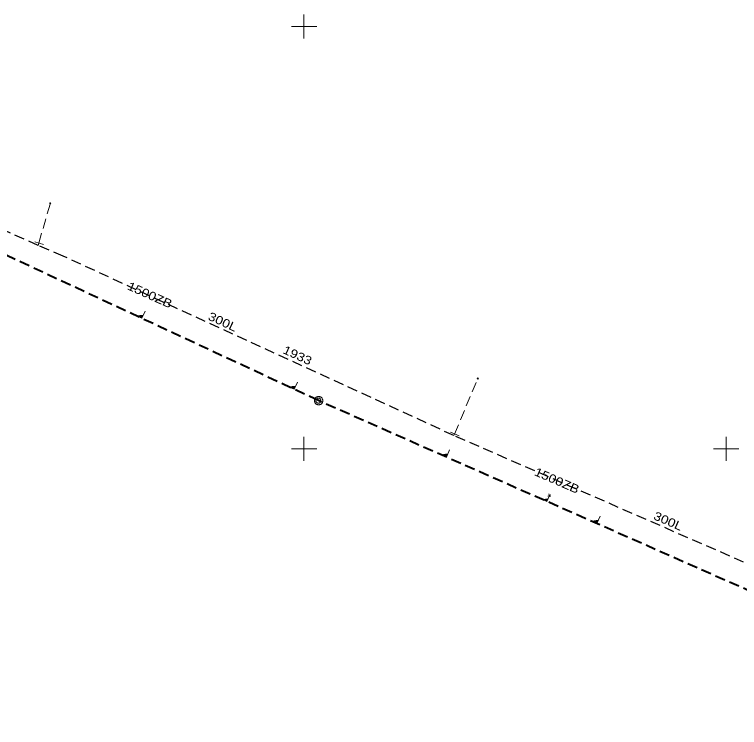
# Model space of a CAD drawing. Extents: x -740851 to -738888, y -1041382 to -1040235.
# Drawn here: x -739134.3 to -739048.4, y -1041333 to -1041248.6 of the extents above; entities that cross this region are included whole.
import ezdxf

# ---------------------------------------------------------------- set-up
doc = ezdxf.new("R2010")
doc.units = 0
doc.header["$LTSCALE"] = 0.4
doc.linetypes.add('MEDIUM_DASHED', pattern=[4.5, 3, -1.5])
for name, color, linetype, lineweight in [('1', 7, 'Continuous', 13), ('18', 7, 'Continuous', 13), ('38', 7, 'Continuous', 13), ('8', 7, 'Continuous', 13)]:
    doc.layers.add(name, color=color, linetype=linetype, lineweight=lineweight)

msp = doc.modelspace()

# ---------------------------------------------------------------- linework, layer by layer
at = {"layer": '1'}
for p, q in [((-739100, -1041248.571), (-739100, -1041251.429)), ((-739101.48, -1041250), (-739098.48, -1041250)), ((-739100, -1041298.571), (-739100, -1041301.429)), ((-739100, -1041298.571), (-739100, -1041301.429)), ((-739050, -1041298.571), (-739050, -1041301.429)), ((-739101.48, -1041300), (-739098.48, -1041300)), ((-739101.48, -1041300), (-739098.48, -1041300)), ((-739051.48, -1041300), (-739048.48, -1041300))]:
    msp.add_line(p, q, dxfattribs=at)
at = {"layer": '18', "linetype": 'MEDIUM_DASHED', "lineweight": 40}
msp.add_line((-739098.28, -1041294.28), (-739139.51, -1041275.09), dxfattribs=at)
at = {"layer": '18'}
for p, q in [((-739070.978, -1041305.324), (-739070.836, -1041305.689)), ((-739071.098, -1041305.578), (-739070.737, -1041305.437))]:
    msp.add_line(p, q, dxfattribs=at)
for points in [[(-739118.808, -1041283.691), (-739119.203, -1041284.539), (-739119.808, -1041284.257), (-739119.025, -1041284.157)], [(-739119.109, -1041284.221), (-739119.224, -1041284.468), (-739119.611, -1041284.288), (-739119.105, -1041284.223)], [(-739119.195, -1041284.289), (-739119.252, -1041284.413), (-739119.451, -1041284.32), (-739119.191, -1041284.291)], [(-739100.767, -1041292.088), (-739101.161, -1041292.936), (-739101.767, -1041292.655), (-739100.983, -1041292.554)], [(-739101.068, -1041292.618), (-739101.182, -1041292.865), (-739101.569, -1041292.685), (-739101.063, -1041292.62)], [(-739101.154, -1041292.686), (-739101.211, -1041292.81), (-739101.409, -1041292.718), (-739101.149, -1041292.688)], [(-739082.74, -1041300.103), (-739083.122, -1041300.968), (-739083.74, -1041300.696), (-739082.95, -1041300.578)], [(-739083.034, -1041300.645), (-739083.145, -1041300.897), (-739083.54, -1041300.722), (-739083.03, -1041300.646)], [(-739083.119, -1041300.715), (-739083.175, -1041300.841), (-739083.377, -1041300.752), (-739083.115, -1041300.717)], [(-739070.91, -1041305.504), (-739071.226, -1041306.22), (-739071.737, -1041305.994), (-739071.083, -1041305.897)], [(-739071.152, -1041305.952), (-739071.244, -1041306.161), (-739071.571, -1041306.016), (-739071.149, -1041305.954)], [(-739071.223, -1041306.011), (-739071.269, -1041306.115), (-739071.437, -1041306.041), (-739071.22, -1041306.012)], [(-739064.901, -1041307.977), (-739065.283, -1041308.843), (-739065.901, -1041308.57), (-739065.111, -1041308.452)], [(-739065.194, -1041308.519), (-739065.306, -1041308.771), (-739065.7, -1041308.597), (-739065.19, -1041308.521)], [(-739065.28, -1041308.59), (-739065.336, -1041308.716), (-739065.538, -1041308.626), (-739065.276, -1041308.592)]]:
    msp.add_lwpolyline(points, dxfattribs=at)
for points in [[(-739097.75, -1041294.29), (-739097.76, -1041294.24), (-739097.76, -1041294.19), (-739097.78, -1041294.14), (-739097.8, -1041294.09), (-739097.82, -1041294.04), (-739097.85, -1041294), (-739097.88, -1041293.96), (-739097.92, -1041293.92), (-739097.96, -1041293.89), (-739098, -1041293.86), (-739098.05, -1041293.84), (-739098.1, -1041293.82), (-739098.15, -1041293.8), (-739098.2, -1041293.8), (-739098.25, -1041293.79), (-739098.3, -1041293.8), (-739098.35, -1041293.8), (-739098.4, -1041293.82), (-739098.45, -1041293.84), (-739098.5, -1041293.86), (-739098.54, -1041293.89), (-739098.58, -1041293.92), (-739098.62, -1041293.96), (-739098.65, -1041294), (-739098.68, -1041294.04), (-739098.7, -1041294.09), (-739098.72, -1041294.14), (-739098.74, -1041294.19), (-739098.74, -1041294.24), (-739098.75, -1041294.29), (-739098.74, -1041294.34), (-739098.74, -1041294.39), (-739098.72, -1041294.44), (-739098.7, -1041294.49), (-739098.68, -1041294.54), (-739098.65, -1041294.58), (-739098.62, -1041294.62), (-739098.58, -1041294.66), (-739098.54, -1041294.69), (-739098.5, -1041294.72), (-739098.45, -1041294.74), (-739098.4, -1041294.76), (-739098.35, -1041294.78), (-739098.3, -1041294.78), (-739098.25, -1041294.79), (-739098.2, -1041294.78), (-739098.15, -1041294.78), (-739098.1, -1041294.76), (-739098.05, -1041294.74), (-739098, -1041294.72), (-739097.96, -1041294.69), (-739097.92, -1041294.66), (-739097.88, -1041294.62), (-739097.85, -1041294.58), (-739097.82, -1041294.54), (-739097.8, -1041294.49), (-739097.78, -1041294.44), (-739097.76, -1041294.39), (-739097.76, -1041294.34)], [(-739097.98, -1041294.28), (-739097.98, -1041294.25), (-739097.986, -1041294.22), (-739097.992, -1041294.19), (-739098.004, -1041294.16), (-739098.022, -1041294.13), (-739098.04, -1041294.106), (-739098.058, -1041294.082), (-739098.082, -1041294.058), (-739098.106, -1041294.04), (-739098.13, -1041294.022), (-739098.16, -1041294.004), (-739098.19, -1041293.992), (-739098.22, -1041293.986), (-739098.25, -1041293.98), (-739098.28, -1041293.98), (-739098.31, -1041293.98), (-739098.34, -1041293.986), (-739098.37, -1041293.992), (-739098.4, -1041294.004), (-739098.43, -1041294.022), (-739098.454, -1041294.04), (-739098.478, -1041294.058), (-739098.502, -1041294.082), (-739098.52, -1041294.106), (-739098.538, -1041294.13), (-739098.556, -1041294.16), (-739098.568, -1041294.19), (-739098.574, -1041294.22), (-739098.58, -1041294.25), (-739098.58, -1041294.28), (-739098.58, -1041294.31), (-739098.574, -1041294.34), (-739098.568, -1041294.37), (-739098.556, -1041294.4), (-739098.538, -1041294.43), (-739098.52, -1041294.454), (-739098.502, -1041294.478), (-739098.478, -1041294.502), (-739098.454, -1041294.52), (-739098.43, -1041294.538), (-739098.4, -1041294.556), (-739098.37, -1041294.568), (-739098.34, -1041294.574), (-739098.31, -1041294.58), (-739098.28, -1041294.58), (-739098.25, -1041294.58), (-739098.22, -1041294.574), (-739098.19, -1041294.568), (-739098.16, -1041294.556), (-739098.13, -1041294.538), (-739098.106, -1041294.52), (-739098.082, -1041294.502), (-739098.058, -1041294.478), (-739098.04, -1041294.454), (-739098.022, -1041294.43), (-739098.004, -1041294.4), (-739097.992, -1041294.37), (-739097.986, -1041294.34), (-739097.98, -1041294.31)]]:
    msp.add_lwpolyline(points, close=True, dxfattribs=at)
at = {"layer": '18', "linetype": 'MEDIUM_DASHED', "lineweight": 40}
msp.add_lwpolyline([(-739015.025, -1041332.979), (-739045.2, -1041317.71), (-739098.28, -1041294.28)], dxfattribs=at)
at = {"layer": '38', "linetype": 'MEDIUM_DASHED'}
for p, q in [((-739131.391, -1041275.625), (-739130.043, -1041270.932)), ((-739131.478, -1041275.908), (-739131.391, -1041275.625)), ((-739082.155, -1041298.235), (-739079.398, -1041291.67)), ((-739082.235, -1041298.419), (-739082.155, -1041298.235))]:
    msp.add_line(p, q, dxfattribs=at)
at = {"layer": '8'}
for p, q in [((-739130.106, -1041270.964), (-739129.981, -1041270.898)), ((-739130.106, -1041270.964), (-739130.1, -1041270.945)), ((-739130.106, -1041270.964), (-739130.087, -1041270.97)), ((-739130.076, -1041270.868), (-739130.082, -1041270.887)), ((-739130.01, -1041270.993), (-739130.076, -1041270.868)), ((-739130.076, -1041270.868), (-739130.057, -1041270.874)), ((-739130.01, -1041270.993), (-739130.03, -1041270.987)), ((-739130.01, -1041270.993), (-739130.005, -1041270.974)), ((-739129.981, -1041270.898), (-739130, -1041270.892)), ((-739129.981, -1041270.898), (-739129.987, -1041270.917)), ((-739130.851, -1041275.791), (-739131.851, -1041275.483)), ((-739079.464, -1041291.695), (-739079.333, -1041291.642)), ((-739079.425, -1041291.603), (-739079.433, -1041291.622)), ((-739079.372, -1041291.734), (-739079.425, -1041291.603)), ((-739079.425, -1041291.603), (-739079.407, -1041291.611)), ((-739079.333, -1041291.642), (-739079.352, -1041291.634)), ((-739079.333, -1041291.642), (-739079.341, -1041291.66)), ((-739079.464, -1041291.695), (-739079.456, -1041291.677)), ((-739079.464, -1041291.695), (-739079.446, -1041291.703)), ((-739079.372, -1041291.734), (-739079.39, -1041291.726)), ((-739079.372, -1041291.734), (-739079.364, -1041291.716)), ((-739081.615, -1041298.47), (-739082.615, -1041298.035))]:
    msp.add_line(p, q, dxfattribs=at)
for points in [[(-739130.029, -1041270.883), (-739130.033, -1041270.881), (-739130.039, -1041270.881), (-739130.044, -1041270.88), (-739130.049, -1041270.881), (-739130.055, -1041270.882), (-739130.059, -1041270.884), (-739130.064, -1041270.886), (-739130.069, -1041270.888), (-739130.073, -1041270.891), (-739130.077, -1041270.894), (-739130.082, -1041270.898), (-739130.085, -1041270.902), (-739130.087, -1041270.907), (-739130.09, -1041270.911), (-739130.091, -1041270.916), (-739130.093, -1041270.921), (-739130.093, -1041270.926), (-739130.094, -1041270.931), (-739130.093, -1041270.936), (-739130.092, -1041270.942), (-739130.09, -1041270.947), (-739130.089, -1041270.951), (-739130.086, -1041270.956), (-739130.083, -1041270.96), (-739130.08, -1041270.964), (-739130.076, -1041270.969), (-739130.072, -1041270.972), (-739130.067, -1041270.975), (-739130.063, -1041270.977), (-739130.058, -1041270.978), (-739130.053, -1041270.98), (-739130.048, -1041270.98), (-739130.043, -1041270.981), (-739130.038, -1041270.981), (-739130.032, -1041270.979), (-739130.028, -1041270.977), (-739130.023, -1041270.976), (-739130.018, -1041270.973), (-739130.014, -1041270.97), (-739130.01, -1041270.967), (-739130.005, -1041270.963), (-739130.002, -1041270.959), (-739130, -1041270.955), (-739129.997, -1041270.95), (-739129.996, -1041270.945), (-739129.994, -1041270.941), (-739129.994, -1041270.936), (-739129.993, -1041270.93), (-739129.994, -1041270.925), (-739129.995, -1041270.919), (-739129.997, -1041270.915), (-739129.998, -1041270.91), (-739130.001, -1041270.905), (-739130.004, -1041270.901), (-739130.007, -1041270.897), (-739130.011, -1041270.893), (-739130.015, -1041270.889), (-739130.019, -1041270.887), (-739130.024, -1041270.884)], [(-739079.379, -1041291.622), (-739079.384, -1041291.621), (-739079.389, -1041291.62), (-739079.394, -1041291.619), (-739079.399, -1041291.618), (-739079.405, -1041291.619), (-739079.41, -1041291.62), (-739079.415, -1041291.622), (-739079.42, -1041291.624), (-739079.424, -1041291.626), (-739079.429, -1041291.629), (-739079.433, -1041291.632), (-739079.437, -1041291.636), (-739079.44, -1041291.64), (-739079.443, -1041291.645), (-739079.445, -1041291.649), (-739079.447, -1041291.654), (-739079.448, -1041291.659), (-739079.449, -1041291.664), (-739079.449, -1041291.669), (-739079.448, -1041291.675), (-739079.447, -1041291.68), (-739079.445, -1041291.685), (-739079.443, -1041291.69), (-739079.441, -1041291.694), (-739079.438, -1041291.699), (-739079.435, -1041291.703), (-739079.431, -1041291.707), (-739079.427, -1041291.71), (-739079.423, -1041291.713), (-739079.418, -1041291.715), (-739079.413, -1041291.717), (-739079.408, -1041291.718), (-739079.403, -1041291.719), (-739079.398, -1041291.719), (-739079.392, -1041291.718), (-739079.387, -1041291.717), (-739079.382, -1041291.715), (-739079.377, -1041291.713), (-739079.373, -1041291.711), (-739079.369, -1041291.708), (-739079.364, -1041291.705), (-739079.36, -1041291.701), (-739079.357, -1041291.697), (-739079.354, -1041291.693), (-739079.352, -1041291.688), (-739079.35, -1041291.683), (-739079.349, -1041291.678), (-739079.348, -1041291.673), (-739079.348, -1041291.668), (-739079.349, -1041291.662), (-739079.35, -1041291.657), (-739079.352, -1041291.652), (-739079.354, -1041291.647), (-739079.356, -1041291.643), (-739079.359, -1041291.639), (-739079.362, -1041291.634), (-739079.366, -1041291.63), (-739079.37, -1041291.627), (-739079.375, -1041291.624)]]:
    msp.add_lwpolyline(points, close=True, dxfattribs=at)
at = {"layer": '8', "linetype": 'MEDIUM_DASHED', "lineweight": 25}
msp.add_lwpolyline([(-739029.766, -1041321.32), (-739082.235, -1041298.419), (-739128.51, -1041277.178), (-739131.478, -1041275.908), (-739142.38, -1041271.06)], dxfattribs=at)

# ---------------------------------------------------------------- texts
at = {"layer": '18', "width": 1.2}
for rotation, p in [(335.852, (-739121.007, -1041281.075)), (336.492, (-739072.805, -1041303.078))]:
    msp.add_text('1500ZB', height=1, rotation=rotation, dxfattribs=at).set_placement(p)
at = {"layer": '8', "width": 1.2}
for s, rotation, p in [('300L', 335.345, (-739111.444, -1041284.656)), ('1933', 335.345, (-739102.589, -1041288.629)), ('300L', 336.419, (-739058.684, -1041308.285))]:
    msp.add_text(s, height=1, rotation=rotation, dxfattribs=at).set_placement(p)

doc.saveas('drawing.dxf')
